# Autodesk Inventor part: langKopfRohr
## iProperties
Created: 2006-10
Part Number: langKopfRohr
Document SubType Name: Sheet Metal
Designer: rr
Author: rr
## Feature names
1. Extrusion1
2. Grobblech1
